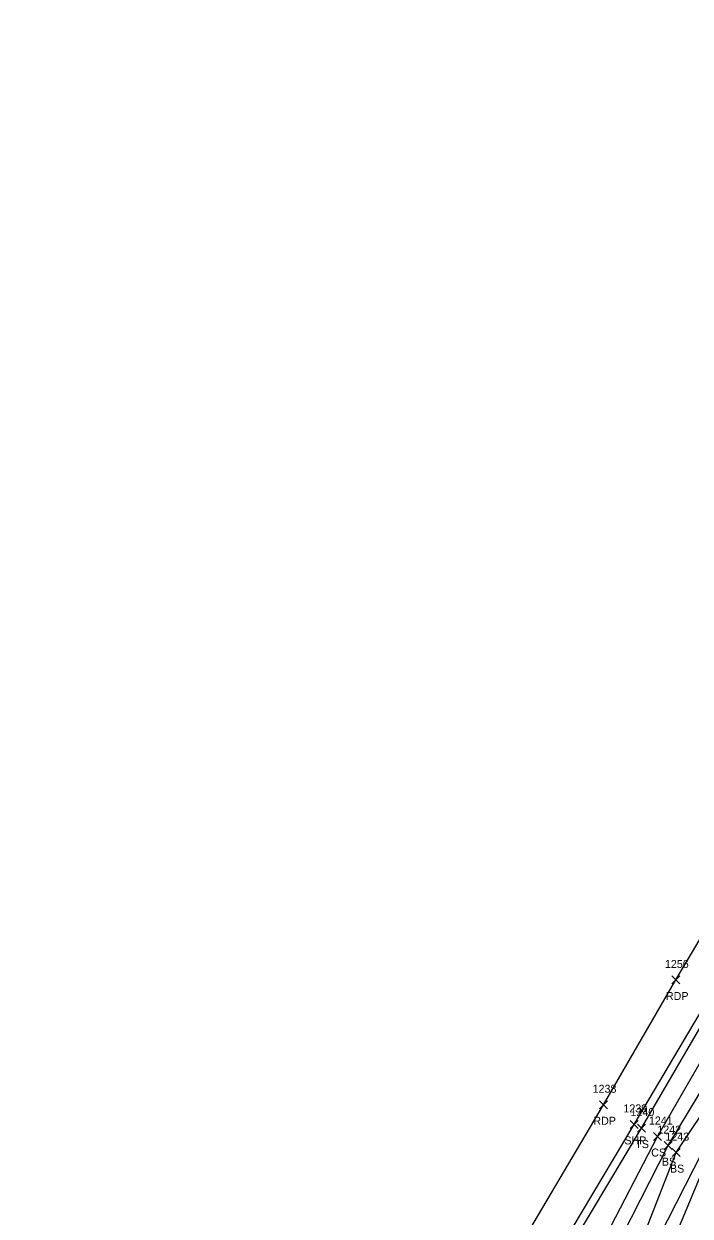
# Model space of a CAD drawing. Extents: x 1483143 to 1488182, y 802902 to 807581.
# Drawn here: x 1487100 to 1487266.4, y 805194.3 to 805492.2 of the extents above; entities that cross this region are included whole.
import ezdxf

# ---------------------------------------------------------------- set-up
doc = ezdxf.new("R2010")
doc.units = 0
for name, color, linetype in [('L_A', 7, 'Continuous'), ('L_I', 7, 'Continuous'), ('L_TIC', 7, 'Continuous'), ('LARO', 7, 'Continuous'), ('LELB', 7, 'Continuous'), ('P_A', 7, 'Continuous'), ('P_I', 7, 'Continuous'), ('P_TIC', 7, 'Continuous'), ('PET', 7, 'Continuous'), ('PSP', 7, 'Continuous')]:
    doc.layers.add(name, color=color, linetype=linetype)

msp = doc.modelspace()

# ---------------------------------------------------------------- linework, layer by layer
at = {"layer": 'L_TIC'}
for points in [[(1487253.33, 805215.27), (1487255.33, 805217.27)], [(1487255.33, 805215.27), (1487253.33, 805217.27)], [(1487257.28, 805213.16), (1487259.28, 805215.16)], [(1487259.28, 805213.16), (1487257.28, 805215.16)], [(1487259.94, 805210.88), (1487261.94, 805212.88)], [(1487261.94, 805210.88), (1487259.94, 805212.88)], [(1487261.97, 805209.14), (1487263.97, 805211.14)], [(1487263.97, 805209.14), (1487261.97, 805211.14)]]:
    msp.add_lwpolyline(points, dxfattribs=at)
at = {"layer": 'LARO'}
msp.add_lwpolyline([(1487124.31, 804973.13), (1487145.49, 805006.81), (1487169.77, 805044.38), (1487180.59, 805057.87), (1487189.8, 805070.17), (1487199.3, 805080.96), (1487217.89, 805101.74), (1487229.45, 805124.32), (1487246.83, 805150.76), (1487254.41, 805169.19), (1487269.28, 805204.96), (1487282.34, 805212.7), (1487284.63, 805226.5), (1487290.62, 805235.83), (1487297.31, 805243.76), (1487306.73, 805267.09), (1487309.81, 805276.71), (1487327.69, 805305.4), (1487333.49, 805320.05), (1487351.27, 805341.81), (1487376.58, 805390.13), (1487400.9, 805431.24), (1487423.77, 805476.17), (1487448.72, 805522.61)], dxfattribs=at)
at = {"layer": 'LELB'}
for points in [[(1487199.3, 805080.96), (1487209.02, 805107.06), (1487224.53, 805127.21), (1487240.95, 805152.24), (1487249.95, 805171.94), (1487269.65, 805210.5), (1487285.86, 805237.33), (1487303.36, 805267.84), (1487322.25, 805302.17), (1487347.45, 805347.07), (1487376.58, 805390.13), (1487398.58, 805433.78), (1487419.88, 805479.75), (1487445.41, 805524.09), (1487470.45, 805569.86), (1487486.06, 805603.16), (1487492.1, 805615.56), (1487500.68, 805632.42), (1487507.33, 805640.17), (1487520.3, 805671.34), (1487528.77, 805686.31), (1487539.17, 805698.49)], [(1487108.71, 804980.78), (1487132.66, 805016.32), (1487156.92, 805053.98), (1487173.31, 805079.98), (1487194.46, 805114.79), (1487207.05, 805135.95), (1487220.86, 805159.73), (1487233.38, 805181.3), (1487254.33, 805216.27), (1487271.44, 805245.69), (1487289.79, 805275.85), (1487308.89, 805309.94), (1487335.6, 805356.15), (1487359.27, 805398.59), (1487383.94, 805443.57), (1487406.66, 805485.41), (1487431.45, 805531.24)], [(1487141.45, 805012.57), (1487160.97, 805051.58), (1487177.59, 805077.87), (1487198.8, 805111.86), (1487211.59, 805133.5), (1487225.91, 805156.73), (1487238.62, 805176.26), (1487258.28, 805214.16), (1487275.11, 805243.36), (1487293.13, 805273.9), (1487313.26, 805307.35), (1487339.04, 805353.08), (1487362.83, 805397.01), (1487388.55, 805442.86), (1487410.04, 805483.24), (1487436.07, 805529.53)], [(1487115.55, 804977.3), (1487141.45, 805012.57), (1487163.51, 805049.72), (1487181.31, 805075.62), (1487202.21, 805110.17), (1487217.83, 805130.45), (1487232, 805156.36), (1487242.54, 805175.79), (1487260.94, 805211.88), (1487278.65, 805241.13), (1487296.94, 805270.92), (1487316.03, 805304.83), (1487341.87, 805350.7), (1487367.6, 805395.34), (1487392.63, 805437.94), (1487413.83, 805481.53), (1487440.22, 805526.89)], [(1487119.27, 804975.75), (1487145.32, 805010.11), (1487166.09, 805047.54), (1487184.56, 805073.64), (1487204.9, 805108.12), (1487221.47, 805128.3), (1487235.08, 805155.22), (1487247.48, 805170.55), (1487262.97, 805210.14), (1487282.96, 805240.11), (1487299.52, 805269.42), (1487319.05, 805303.47), (1487344.42, 805349.03), (1487372.12, 805390.86), (1487397.58, 805436.46), (1487417, 805480.8), (1487442.28, 805525.8)]]:
    msp.add_lwpolyline(points, dxfattribs=at)
at = {"layer": 'P_TIC'}
for points in [[(1487261.9, 805252.28), (1487263.9, 805254.28)], [(1487263.9, 805252.28), (1487261.9, 805254.28)], [(1487243.77, 805221.1), (1487245.77, 805223.1)], [(1487245.77, 805221.1), (1487243.77, 805223.1)], [(1487251.47, 805216.19), (1487253.47, 805218.19)], [(1487253.47, 805216.19), (1487251.47, 805218.19)]]:
    msp.add_lwpolyline(points, dxfattribs=at)
at = {"layer": 'PET'}
msp.add_lwpolyline([(1487100.01, 804984.32), (1487124.37, 805022.55), (1487148.19, 805060.93), (1487163.62, 805085.69), (1487185.29, 805121.77), (1487197.78, 805142.12), (1487211.62, 805165.78), (1487224.01, 805186.83), (1487244.77, 805222.1), (1487262.9, 805253.28), (1487279.63, 805281.48), (1487299.46, 805315.66), (1487325.71, 805361.73), (1487348.03, 805401.83), (1487373.61, 805448.47), (1487396.33, 805490.41), (1487421.9, 805537.94)], dxfattribs=at)
at = {"layer": 'PSP'}
msp.add_lwpolyline([(1487105.23, 804982.13), (1487129.96, 805018.35), (1487154.68, 805055.53), (1487171.02, 805081.93), (1487192.51, 805116.63), (1487204.72, 805136.95), (1487219.03, 805160.88), (1487231.84, 805182.51), (1487252.47, 805217.19), (1487269.89, 805246.6), (1487288.3, 805277.02), (1487307.74, 805310.87), (1487334.08, 805357.49), (1487356.35, 805397.12), (1487382.38, 805444.5), (1487405.03, 805486.21), (1487429.8, 805532.42)], dxfattribs=at)

# ---------------------------------------------------------------- texts
at = {"layer": 'L_A'}
for s, p in [('TS', (1487252.74, 805211.27)), ('CS', (1487256.72, 805209.16)), ('BS', (1487259.38, 805206.88)), ('BS', (1487261.41, 805205.14))]:
    msp.add_text(s, height=2, dxfattribs=at).set_placement(p)
at = {"layer": 'L_I'}
for s, p in [('1240', (1487251.55, 805219.27)), ('1241', (1487256.15, 805217.16)), ('1242', (1487258.25, 805214.88)), ('1243', (1487260.27, 805213.14))]:
    msp.add_text(s, height=2, dxfattribs=at).set_placement(p)
at = {"layer": 'P_A'}
for s, p in [('RDP', (1487260.39, 805248.28)), ('RDP', (1487242.26, 805217.1)), ('SHP', (1487250.01, 805212.19))]:
    msp.add_text(s, height=2, dxfattribs=at).set_placement(p)
at = {"layer": 'P_I'}
for s, p in [('1256', (1487260.15, 805256.28)), ('1238', (1487242.08, 805225.1)), ('1239', (1487249.77, 805220.19))]:
    msp.add_text(s, height=2, dxfattribs=at).set_placement(p)

doc.saveas('drawing.dxf')
